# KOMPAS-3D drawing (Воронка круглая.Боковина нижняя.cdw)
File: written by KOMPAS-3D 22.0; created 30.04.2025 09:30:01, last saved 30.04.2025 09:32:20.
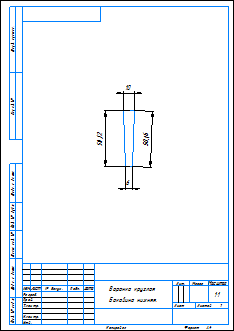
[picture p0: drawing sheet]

Sheet 1: A4, portrait

Document properties: Автор: Admin; Наименование: Воронка круглая Боковина нижняя; Полное имя файла: D:\28.11.2016\3D модели\Абилимпикс\2025\Воронка круглая\Воронка круглая Боковина нижняя..cdw

Title block, sheet 1: Наименование: Воронка круглая / Боковина нижняя.; scale: 1:1; Количество листов документа: 1; Форматы листов документа: A4; stored path: D:\28.11.2016\3D модели\Абилимпикс\2025\Воронка круглая\Воронка круглая Боковина верхняя..cdw

Dimensions and other numbers on the sheet: 10; 6; 50,12; 50,16; 1:1; 1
